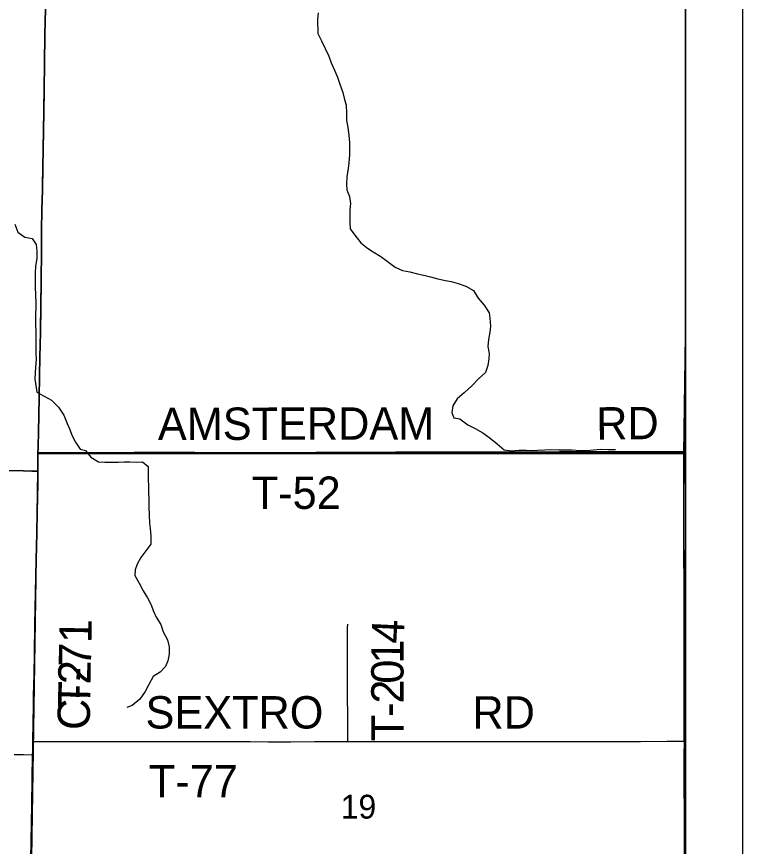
# Model space of a CAD drawing. Extents: x 0 to 34, y 0 to 22.
# Drawn here: x 7.725 to 9, y 15.728 to 17.185 of the extents above; entities that cross this region are included whole.
import ezdxf

# ---------------------------------------------------------------- set-up
doc = ezdxf.new("R2010")
doc.units = 0
for name, color, linetype in [('GM_X_Corporation', 7, 'Continuous'), ('GM_X_County_Road', 7, 'Continuous'), ('GM_X_County_Road_Text', 7, 'Continuous'), ('GM_X_Minor_River', 7, 'Continuous'), ('GM_X_Section_Text', 7, 'Continuous'), ('GM_X_Township_Road', 7, 'Continuous'), ('GM_X_Township_Road_Text', 7, 'Continuous'), ('SH_Data', 7, 'Continuous')]:
    doc.layers.add(name, color=color, linetype=linetype)

msp = doc.modelspace()

# ---------------------------------------------------------------- linework, layer by layer
at = {"layer": 'GM_X_Corporation'}
for points in [[(7.7759, 17.1994), (7.7755, 17.1752), (7.7751, 17.1534), (7.7742, 17.1025), (7.7735, 17.0571), (7.7729, 17.0174), (7.7717, 16.9515), (7.7712, 16.9217), (7.7705, 16.88), (7.7698, 16.8465), (7.7693, 16.8086), (7.7692, 16.7955), (7.7689, 16.7726), (7.7676, 16.6719), (7.767, 16.6334), (7.7664, 16.606), (7.7661, 16.5899), (7.7654, 16.5514), (7.7649, 16.5184), (7.7641, 16.4824), (7.7635, 16.4575), (7.7629, 16.4283), (7.7628, 16.4188), (7.7638, 16.4189), (7.7742, 16.419), (7.799, 16.4191), (7.8493, 16.4188), (7.894, 16.4191), (7.9319, 16.4193), (7.9618, 16.4192), (8.0133, 16.4193), (8.0382, 16.4192), (8.0972, 16.419), (8.1532, 16.4191), (8.2514, 16.4193), (8.2986, 16.4193), (8.3402, 16.4195), (8.3906, 16.4198), (8.4595, 16.4203), (8.5242, 16.4201), (8.582, 16.4202), (8.6124, 16.4202), (8.641, 16.4203), (8.6458, 16.4203), (8.6795, 16.4204), (8.7199, 16.4206), (8.7628, 16.4208), (8.7901, 16.4206), (8.8318, 16.4206), (8.8815, 16.4206), (8.8974, 16.4207), (8.9, 16.4207), (8.9, 20.4201)], [(8.9, 14.1), (8.9, 20.4201)], [(6.7715, 16.4096), (7.7624, 16.3866), (7.7624, 16.3911), (7.7628, 16.4188), (7.7629, 16.4283), (7.7635, 16.4575), (7.7641, 16.4824), (7.7649, 16.5184), (7.7654, 16.5514), (7.7661, 16.5899), (7.7664, 16.606), (7.767, 16.6334), (7.7676, 16.6719), (7.7689, 16.7726), (7.7692, 16.7955), (7.7693, 16.8086), (7.7698, 16.8465), (7.7705, 16.88), (7.7712, 16.9217), (7.7717, 16.9515), (7.7729, 17.0174), (7.7735, 17.0571), (7.7742, 17.1025), (7.7751, 17.1534), (7.7755, 17.1752), (7.7759, 17.1994)], [(7.7759, 17.1994), (7.7755, 17.1752), (7.7751, 17.1534), (7.7742, 17.1025), (7.7735, 17.0571), (7.7729, 17.0174), (7.7717, 16.9515), (7.7712, 16.9217), (7.7705, 16.88), (7.7698, 16.8465), (7.7693, 16.8086), (7.7692, 16.7955), (7.7689, 16.7726), (7.7676, 16.6719), (7.767, 16.6334), (7.7664, 16.606), (7.7661, 16.5899), (7.7654, 16.5514), (7.7649, 16.5184), (7.7641, 16.4824), (7.7635, 16.4575), (7.7629, 16.4283), (7.7628, 16.4188), (7.7624, 16.3911), (7.7624, 16.3866), (7.7623, 16.3643), (7.7613, 16.3153), (7.7606, 16.278), (7.7599, 16.2314), (7.7587, 16.173), (7.7574, 16.1171), (7.7566, 16.0661), (7.7559, 16.0301), (7.7552, 15.9922), (7.7549, 15.9779), (7.7541, 15.9412), (7.7538, 15.9164), (7.7537, 15.9122), (7.7535, 15.894), (7.7534, 15.889), (7.7529, 15.8449), (7.7522, 15.802), (7.7516, 15.7672), (7.751, 15.7381), (7.7505, 15.7051)], [(7.7505, 15.7051), (7.751, 15.7381), (7.7516, 15.7672), (7.7522, 15.802), (7.7529, 15.8449), (7.7534, 15.889), (7.7535, 15.894), (7.7537, 15.9122), (7.7538, 15.9164), (7.7541, 15.9412), (7.7549, 15.9779), (7.7552, 15.9922), (7.7559, 16.0301), (7.7566, 16.0661), (7.7574, 16.1171), (7.7587, 16.173), (7.7599, 16.2314), (7.7606, 16.278), (7.7613, 16.3153), (7.7623, 16.3643), (7.7624, 16.3866), (7.7624, 16.3911), (7.7628, 16.4188), (7.7629, 16.4283), (7.7635, 16.4575), (7.7641, 16.4824), (7.7649, 16.5184), (7.7654, 16.5514), (7.7661, 16.5899), (7.7664, 16.606), (7.767, 16.6334), (7.7676, 16.6719), (7.7689, 16.7726), (7.7692, 16.7955), (7.7693, 16.8086), (7.7698, 16.8465), (7.7705, 16.88), (7.7712, 16.9217), (7.7717, 16.9515), (7.7729, 17.0174), (7.7735, 17.0571), (7.7742, 17.1025), (7.7751, 17.1534), (7.7755, 17.1752), (7.7759, 17.1994)], [(8.9, 14.1), (8.9, 16.4207), (8.8974, 16.4207), (8.8815, 16.4206), (8.8318, 16.4206), (8.7901, 16.4206), (8.7628, 16.4208), (8.7199, 16.4206), (8.6795, 16.4204), (8.6458, 16.4203), (8.641, 16.4203), (8.6124, 16.4202), (8.582, 16.4202), (8.5242, 16.4201), (8.4595, 16.4203), (8.3906, 16.4198), (8.3402, 16.4195), (8.2986, 16.4193), (8.2514, 16.4193), (8.1532, 16.4191), (8.0972, 16.419), (8.0382, 16.4192), (8.0133, 16.4193), (7.9618, 16.4192), (7.9319, 16.4193), (7.894, 16.4191), (7.8493, 16.4188), (7.799, 16.4191), (7.7742, 16.419), (7.7638, 16.4189), (7.7628, 16.4188), (7.7624, 16.3911), (7.7624, 16.3866), (7.7623, 16.3643), (7.7613, 16.3153), (7.7606, 16.278), (7.7599, 16.2314), (7.7587, 16.173), (7.7574, 16.1171), (7.7566, 16.0661), (7.7559, 16.0301), (7.7552, 15.9922), (7.7549, 15.9779), (7.7541, 15.9412), (7.7538, 15.9164), (7.7537, 15.9122), (7.7535, 15.894), (7.7534, 15.889), (7.7529, 15.8449), (7.7522, 15.802), (7.7516, 15.7672), (7.751, 15.7381), (7.7505, 15.7051)], [(7.7505, 15.7051), (7.751, 15.7381), (7.7516, 15.7672), (7.7522, 15.802), (7.7529, 15.8449), (7.7534, 15.889), (7.7535, 15.894), (7.7537, 15.9122), (7.7538, 15.9164), (7.7541, 15.9412), (7.7549, 15.9779), (7.7552, 15.9922), (7.7559, 16.0301), (7.7566, 16.0661), (7.7574, 16.1171), (7.7587, 16.173), (7.7599, 16.2314), (7.7606, 16.278), (7.7613, 16.3153), (7.7623, 16.3643), (7.7624, 16.3866), (6.7715, 16.4096)]]:
    msp.add_lwpolyline(points, dxfattribs=at)
for points in [[(8.9, 16.4176), (8.9, 16.6672), (8.8965, 16.4176)], [(8.8965, 16.4176), (8.8984, 15.4027), (7.7473, 15.4057), (7.7624, 16.3866), (7.7629, 16.4174)], [(8.9, 15.4027), (8.9, 16.4176), (8.8965, 16.4176), (8.8984, 15.4027)]]:
    msp.add_lwpolyline(points, close=True, dxfattribs=at)
at = {"layer": 'GM_X_County_Road'}
msp.add_line((7.7536, 15.8885), (7.7539, 15.9116), dxfattribs=at)
for points in [[(7.763, 16.4183), (7.7631, 16.4278), (7.7638, 16.457), (7.7641, 16.4694), (7.7644, 16.4818), (7.7652, 16.5179), (7.7654, 16.5344), (7.7657, 16.5508), (7.766, 16.5695), (7.7663, 16.5893), (7.7667, 16.6055), (7.767, 16.6192), (7.7672, 16.6328), (7.7675, 16.6515), (7.7677, 16.6614), (7.7679, 16.6713), (7.7681, 16.69), (7.7683, 16.7086), (7.7686, 16.7273), (7.7689, 16.759), (7.7691, 16.772), (7.7695, 16.795), (7.7698, 16.8267), (7.77, 16.8459), (7.7707, 16.8795), (7.771, 16.8981), (7.7712, 16.9096), (7.7719, 16.951), (7.7726, 16.9882), (7.7731, 17.0168), (7.7734, 17.0355), (7.7736, 17.046), (7.7737, 17.0566), (7.774, 17.0752), (7.7743, 17.0886), (7.7748, 17.1206), (7.7753, 17.1529), (7.7757, 17.1746), (7.7761, 17.1989)], [(7.7626, 16.3861), (7.7628, 16.4044), (7.763, 16.4183)], [(7.7129, 16.388), (7.7275, 16.3876), (7.742, 16.3871), (7.7523, 16.3866), (7.7626, 16.3861)], [(7.7539, 15.9116), (7.7542, 15.9283), (7.7544, 15.9407), (7.7548, 15.959), (7.7551, 15.9773), (7.7554, 15.9916), (7.756, 16.0199), (7.7561, 16.0295), (7.7569, 16.0656), (7.7572, 16.0842), (7.7574, 16.1004), (7.7577, 16.1165), (7.7581, 16.1352), (7.7585, 16.1538), (7.759, 16.1724), (7.7601, 16.2308), (7.7604, 16.2495), (7.7606, 16.2635), (7.7609, 16.2774), (7.7612, 16.2961), (7.7614, 16.3054), (7.7615, 16.3147), (7.7619, 16.3334), (7.7622, 16.3486), (7.7625, 16.3638), (7.7626, 16.3749), (7.7626, 16.3861)], [(7.7211, 15.8891), (7.7374, 15.8888), (7.7536, 15.8885)], [(7.7508, 15.7046), (7.7512, 15.7375), (7.7518, 15.7667), (7.7524, 15.8015), (7.7527, 15.8201), (7.7531, 15.8444), (7.7533, 15.863), (7.7535, 15.8757), (7.7536, 15.8885)]]:
    msp.add_lwpolyline(points, dxfattribs=at)
at = {"layer": 'GM_X_Minor_River'}
for points in [[(8.2549, 17.1916), (8.2536, 17.1798), (8.2546, 17.1554), (8.2605, 17.1424), (8.2671, 17.1289), (8.2734, 17.1155), (8.2777, 17.104), (8.2836, 17.0909), (8.2891, 17.0786), (8.2927, 17.0664), (8.2982, 17.0514), (8.3003, 17.0419), (8.3043, 17.0296), (8.3048, 17.0155), (8.3045, 17.003), (8.3073, 16.99), (8.309, 16.977), (8.3099, 16.9636), (8.3101, 16.953), (8.3099, 16.9427)], [(8.3099, 16.9427), (8.3089, 16.9283), (8.3076, 16.9184), (8.3054, 16.9036), (8.3044, 16.8906), (8.305, 16.8807), (8.3101, 16.8688), (8.3118, 16.8566), (8.3108, 16.8456), (8.3106, 16.8361), (8.3108, 16.8235), (8.3114, 16.8125), (8.3192, 16.8009), (8.33, 16.7878), (8.3413, 16.7784), (8.3518, 16.7721), (8.3647, 16.7639), (8.3759, 16.7553), (8.3903, 16.7451), (8.4031, 16.7388), (8.4157, 16.737), (8.4293, 16.733), (8.443, 16.7301), (8.4525, 16.728), (8.4651, 16.7247), (8.4787, 16.7214), (8.4886, 16.7197), (8.5008, 16.716), (8.514, 16.7116), (8.5276, 16.7037), (8.5362, 16.6906), (8.5463, 16.6783), (8.5555, 16.6648), (8.5565, 16.6552), (8.5574, 16.6415), (8.5565, 16.6309), (8.5539, 16.618), (8.5529, 16.6054), (8.555, 16.5936), (8.5548, 16.5841), (8.5527, 16.572), (8.549, 16.5598), (8.5366, 16.5487), (8.5246, 16.5367), (8.5114, 16.524), (8.4993, 16.5136), (8.4915, 16.5015), (8.4897, 16.4898), (8.4934, 16.4802), (8.5037, 16.4785), (8.518, 16.4683), (8.5308, 16.4616), (8.5444, 16.4537), (8.5572, 16.4448), (8.5692, 16.4346), (8.5816, 16.4241), (8.5942, 16.4224), (8.6072, 16.4233), (8.6206, 16.4238), (8.6301, 16.4232), (8.64, 16.4238), (8.653, 16.4243), (8.6637, 16.4249), (8.6774, 16.4242), (8.6881, 16.4244), (8.7007, 16.4242), (8.7148, 16.4232), (8.7259, 16.423), (8.7385, 16.4243), (8.7507, 16.4252), (8.7641, 16.4245), (8.777, 16.4247)], [(7.7223, 16.8204), (7.7272, 16.8062), (7.7395, 16.7979), (7.7527, 16.7953), (7.7597, 16.7845), (7.7609, 16.773), (7.7606, 16.7609), (7.7587, 16.7461), (7.758, 16.7355), (7.7577, 16.7233), (7.7577, 16.71), (7.7585, 16.6963), (7.7589, 16.6819), (7.7582, 16.6553), (7.7583, 16.6443), (7.7591, 16.6321), (7.7592, 16.6181), (7.7592, 16.607), (7.7593, 16.5934), (7.7594, 16.5827), (7.7586, 16.5691), (7.758, 16.5592), (7.7573, 16.5482), (7.761, 16.5255)], [(7.7609, 16.5255), (7.7868, 16.5113), (7.7988, 16.4989), (7.8085, 16.485), (7.8143, 16.4704), (7.8187, 16.46), (7.822, 16.4497), (7.8286, 16.4374), (7.8368, 16.4254), (7.8463, 16.423), (7.8556, 16.4114), (7.8692, 16.4032), (7.8802, 16.4026), (7.8913, 16.4027), (7.9043, 16.4025), (7.9142, 16.4031), (7.9241, 16.4033), (7.9367, 16.4026), (7.9463, 16.4028), (7.9564, 16.395), (7.9566, 16.3825), (7.9564, 16.3726), (7.9569, 16.36), (7.9567, 16.3498), (7.9573, 16.3376), (7.9574, 16.3242), (7.9583, 16.3094), (7.9588, 16.2953), (7.9597, 16.2858), (7.961, 16.2724), (7.9608, 16.2587), (7.9525, 16.2467), (7.9432, 16.2351), (7.9368, 16.2234), (7.9336, 16.2132), (7.9327, 16.2037), (7.9404, 16.1902), (7.9478, 16.1764), (7.9552, 16.1641), (7.9618, 16.1518), (7.9651, 16.1422), (7.9702, 16.1303), (7.9787, 16.1172), (7.9827, 16.1046), (7.9901, 16.0904), (7.9933, 16.0781), (7.993, 16.0652), (7.9909, 16.0535), (7.9869, 16.0436), (7.9776, 16.0335), (7.9652, 16.0258), (7.9577, 16.0122), (7.951, 15.9998), (7.9416, 15.9863), (7.9284, 15.9751), (7.9188, 15.9715)]]:
    msp.add_lwpolyline(points, dxfattribs=at)
at = {"layer": 'GM_X_Township_Road'}
for p, q in [((8.8976, 16.4202), (8.9, 16.4202)), ((7.7536, 15.8885), (7.7539, 15.9116))]:
    msp.add_line(p, q, dxfattribs=at)
for points in [[(7.763, 16.4183), (7.7631, 16.4278), (7.7638, 16.457), (7.7641, 16.4694), (7.7644, 16.4818), (7.7652, 16.5179), (7.7654, 16.5344), (7.7657, 16.5508), (7.766, 16.5695), (7.7663, 16.5893), (7.7667, 16.6055), (7.767, 16.6192), (7.7672, 16.6328), (7.7675, 16.6515), (7.7677, 16.6614), (7.7679, 16.6713), (7.7681, 16.69), (7.7683, 16.7086), (7.7686, 16.7273), (7.7689, 16.759), (7.7691, 16.772), (7.7695, 16.795), (7.7698, 16.8267), (7.77, 16.8459), (7.7707, 16.8795), (7.771, 16.8981), (7.7712, 16.9096), (7.7719, 16.951), (7.7726, 16.9882), (7.7731, 17.0168), (7.7734, 17.0355), (7.7736, 17.046), (7.7737, 17.0566), (7.774, 17.0752), (7.7743, 17.0886), (7.7748, 17.1206), (7.7753, 17.1529), (7.7757, 17.1746), (7.7761, 17.1989)], [(8.8976, 16.4202), (8.8983, 16.4451), (8.8985, 16.465), (8.8988, 16.4843), (8.8992, 16.5153), (8.8995, 16.5501), (8.8996, 16.5737), (8.8998, 16.5986), (8.9, 16.6136)], [(7.7626, 16.3861), (7.7628, 16.4044), (7.763, 16.4183)], [(7.763, 16.4183), (7.7744, 16.4185), (7.7992, 16.4185), (7.8495, 16.4183), (7.8943, 16.4186), (7.9322, 16.4188), (7.962, 16.4187), (8.0136, 16.4187), (8.0384, 16.4187), (8.0975, 16.4185), (8.1534, 16.4186), (8.2516, 16.4187), (8.2988, 16.4188), (8.3404, 16.4189), (8.3908, 16.4193), (8.3928, 16.4193)], [(8.3928, 16.4193), (8.4598, 16.4198), (8.5244, 16.4195), (8.5822, 16.4197), (8.6126, 16.4197), (8.6412, 16.4198), (8.646, 16.4198), (8.6798, 16.4199), (8.7201, 16.4201), (8.763, 16.4203), (8.7904, 16.4201), (8.832, 16.42), (8.8817, 16.4201), (8.8976, 16.4202)], [(8.8981, 15.9123), (8.8982, 15.9469), (8.8983, 15.9761), (8.8985, 15.9985), (8.8987, 16.0345), (8.8987, 16.0531), (8.8988, 16.0855), (8.8987, 16.096), (8.8983, 16.1259), (8.8976, 16.1593), (8.8975, 16.1742), (8.8975, 16.2009), (8.8974, 16.2295), (8.8974, 16.2755), (8.8974, 16.2891), (8.8974, 16.3034), (8.8974, 16.332), (8.8974, 16.3525), (8.8975, 16.3761), (8.8975, 16.4148), (8.8976, 16.4202)], [(7.7539, 15.9116), (7.7542, 15.9283), (7.7544, 15.9407), (7.7548, 15.959), (7.7551, 15.9773), (7.7554, 15.9916), (7.756, 16.0199), (7.7561, 16.0295), (7.7569, 16.0656), (7.7572, 16.0842), (7.7574, 16.1004), (7.7577, 16.1165), (7.7581, 16.1352), (7.7585, 16.1538), (7.759, 16.1724), (7.7601, 16.2308), (7.7604, 16.2495), (7.7606, 16.2635), (7.7609, 16.2774), (7.7612, 16.2961), (7.7614, 16.3054), (7.7615, 16.3147), (7.7619, 16.3334), (7.7622, 16.3486), (7.7625, 16.3638), (7.7626, 16.3749), (7.7626, 16.3861)], [(8.307, 15.9118), (8.307, 15.9167), (8.307, 15.9529), (8.3069, 15.9635), (8.3064, 15.984), (8.3063, 15.9933), (8.3063, 16.0083), (8.3063, 16.0331), (8.3063, 16.0468), (8.3063, 16.0549), (8.3063, 16.0611), (8.3062, 16.0723), (8.3062, 16.1115), (8.307, 16.1181)], [(7.7539, 15.9116), (7.7606, 15.9117), (7.7644, 15.9118), (7.7861, 15.9116), (7.8141, 15.9117), (7.8396, 15.9117), (7.8868, 15.9116), (7.9371, 15.9117), (7.9744, 15.9117), (7.9812, 15.9118), (7.9918, 15.9117), (8.0098, 15.9116), (8.0452, 15.9119), (8.1049, 15.9118), (8.1223, 15.9118), (8.1353, 15.9117), (8.167, 15.9114), (8.1962, 15.9114), (8.2067, 15.9114), (8.2484, 15.9118), (8.2689, 15.9119), (8.2981, 15.9118), (8.307, 15.9118)], [(8.307, 15.9118), (8.326, 15.9117), (8.3422, 15.9118), (8.3596, 15.912), (8.3807, 15.9119), (8.4006, 15.9118), (8.4074, 15.9119), (8.4391, 15.9119), (8.4497, 15.9118), (8.4627, 15.9121), (8.4956, 15.9119), (8.5031, 15.9119), (8.5323, 15.912), (8.5367, 15.912), (8.5509, 15.9121), (8.5572, 15.9121), (8.5677, 15.9121), (8.5882, 15.912), (8.5944, 15.912), (8.6485, 15.9119), (8.6671, 15.9119), (8.6746, 15.9118), (8.7025, 15.9118), (8.7249, 15.9117), (8.7361, 15.9116), (8.7641, 15.9119), (8.7864, 15.912), (8.7901, 15.912), (8.7995, 15.9121), (8.8212, 15.912), (8.8678, 15.9122), (8.8834, 15.9123), (8.8933, 15.9123), (8.8981, 15.9123)], [(8.8991, 15.4042), (8.8993, 15.4231), (8.8994, 15.443), (8.8992, 15.466), (8.8993, 15.4858), (8.8993, 15.4989), (8.8992, 15.5244), (8.8992, 15.5486), (8.899, 15.5834), (8.8989, 15.6126), (8.8989, 15.6288), (8.8988, 15.6505), (8.8988, 15.6692), (8.8987, 15.6953), (8.8984, 15.7325), (8.8983, 15.7599), (8.8982, 15.8015), (8.898, 15.8214), (8.898, 15.8599), (8.898, 15.8742), (8.8979, 15.8866), (8.8981, 15.9123)], [(7.7508, 15.7046), (7.7512, 15.7375), (7.7518, 15.7667), (7.7524, 15.8015), (7.7527, 15.8201), (7.7531, 15.8444), (7.7533, 15.863), (7.7535, 15.8757), (7.7536, 15.8885)]]:
    msp.add_lwpolyline(points, dxfattribs=at)
at = {"layer": 'SH_Data'}
for p, q in [((9, 21), (9, 14)), ((8.9, 20.9), (8.9, 14.1)), ((8.9, 20.9), (8.9, 14.1))]:
    msp.add_line(p, q, dxfattribs=at)

# ---------------------------------------------------------------- texts
at = {"layer": 'GM_X_County_Road_Text'}
msp.add_text('C-2', height=0.05682, rotation=89.0809, dxfattribs=at).set_placement((7.8537, 15.9317))
at = {"layer": 'GM_X_Section_Text'}
msp.add_text('19', height=0.04186, rotation=0, dxfattribs=at).set_placement((8.2946, 15.7765))
at = {"layer": 'GM_X_Township_Road_Text'}
for s, height, rotation, p in [('AMSTERDAM', 0.05682, 0.1049, (7.9734, 16.4413)), ('RD', 0.05682, 0.4864, (8.7435, 16.4421)), ('T-52', 0.05682, 0, (8.1383, 16.3204)), ('T-71', 0.05682, 88.9465, (7.8546, 15.9706)), ('4', 0.0568, 87.3242, (8.405, 16.0828)), ('1', 0.0568, 89.6878, (8.4048, 16.0484)), ('0', 0.0568, 90.0989, (8.4049, 16.0135)), ('2', 0.0568, 90.2186, (8.405, 15.9786)), ('SEXTRO', 0.05682, 0, (7.9517, 15.9347)), ('RD', 0.05682, 0, (8.5258, 15.9346)), ('-', 0.0568, 90.2449, (8.4051, 15.9552)), ('T', 0.0568, 90.2357, (8.4053, 15.9127)), ('T-77', 0.05682, 0, (7.9575, 15.8138))]:
    msp.add_text(s, height=height, rotation=rotation, dxfattribs=at).set_placement(p)

doc.saveas('drawing.dxf')
